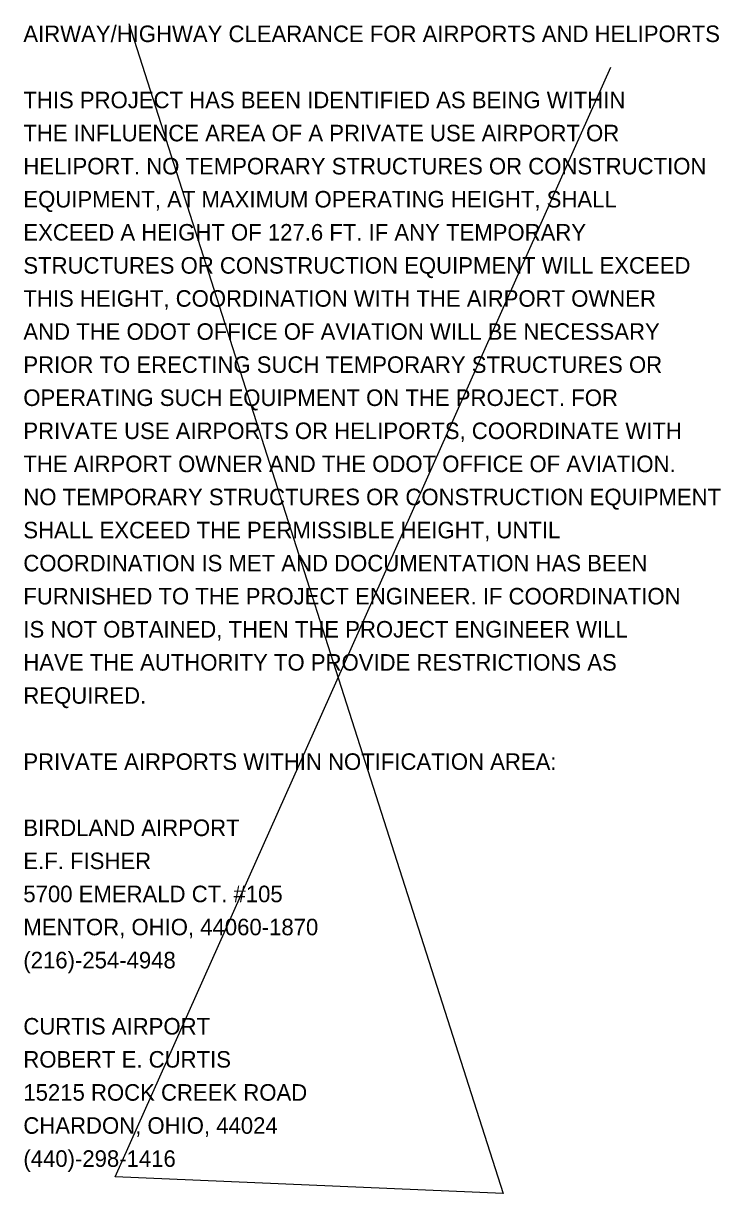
# Model space of a CAD drawing. Extents: x 0 to 55.9, y -18.9 to 33.1.
# Drawn here: x 49.99 to 55.9, y -18.87 to -8.96 of the extents above; entities that cross this region are included whole.
import ezdxf

# ---------------------------------------------------------------- set-up
doc = ezdxf.new("R2010")
doc.units = 0
doc.layers.add('SH_Text', color=7, linetype='Continuous')

msp = doc.modelspace()

# ---------------------------------------------------------------- linework, layer by layer
at = {"layer": 'SH_Text'}
msp.add_lwpolyline([(50.8855, -8.9619), (54.0546, -18.8663), (50.7683, -18.7247), (54.9666, -9.333)], dxfattribs=at)

# ---------------------------------------------------------------- texts
for s, p in [('AIRWAY/HIGHWAY CLEARANCE FOR AIRPORTS AND HELIPORTS', (49.9915, -9.12)), ('THIS PROJECT HAS BEEN IDENTIFIED AS BEING WITHIN', (49.9915, -9.68)), ('THE INFLUENCE AREA OF A PRIVATE USE AIRPORT OR', (49.9915, -9.96)), ('HELIPORT. NO TEMPORARY STRUCTURES OR CONSTRUCTION', (49.9915, -10.24)), ('EQUIPMENT, AT MAXIMUM OPERATING HEIGHT, SHALL', (49.9915, -10.52)), ('EXCEED A HEIGHT OF 127.6 FT. IF ANY TEMPORARY', (49.9915, -10.8)), ('STRUCTURES OR CONSTRUCTION EQUIPMENT WILL EXCEED', (49.9915, -11.08)), ('THIS HEIGHT, COORDINATION WITH THE AIRPORT OWNER', (49.9915, -11.36)), ('AND THE ODOT OFFICE OF AVIATION WILL BE NECESSARY', (49.9915, -11.64)), ('PRIOR TO ERECTING SUCH TEMPORARY STRUCTURES OR', (49.9915, -11.92)), ('OPERATING SUCH EQUIPMENT ON THE PROJECT. FOR', (49.9915, -12.2)), ('PRIVATE USE AIRPORTS OR HELIPORTS, COORDINATE WITH', (49.9915, -12.48)), ('THE AIRPORT OWNER AND THE ODOT OFFICE OF AVIATION.', (49.9915, -12.76)), ('NO TEMPORARY STRUCTURES OR CONSTRUCTION EQUIPMENT', (49.9915, -13.04)), ('SHALL EXCEED THE PERMISSIBLE HEIGHT, UNTIL', (49.9915, -13.32)), ('COORDINATION IS MET AND DOCUMENTATION HAS BEEN', (49.9915, -13.6)), ('FURNISHED TO THE PROJECT ENGINEER. IF COORDINATION', (49.9915, -13.88)), ('IS NOT OBTAINED, THEN THE PROJECT ENGINEER WILL', (49.9915, -14.16)), ('HAVE THE AUTHORITY TO PROVIDE RESTRICTIONS AS', (49.9915, -14.44)), ('REQUIRED.', (49.9915, -14.72)), ('PRIVATE AIRPORTS WITHIN NOTIFICATION AREA:', (49.9915, -15.28)), ('BIRDLAND AIRPORT', (49.9915, -15.84)), ('E.F. FISHER', (49.9915, -16.12)), ('5700 EMERALD CT. #105 ', (49.9915, -16.4)), ('MENTOR, OHIO, 44060-1870', (49.9915, -16.68)), ('(216)-254-4948', (49.9915, -16.96)), ('CURTIS AIRPORT', (49.9915, -17.52)), ('ROBERT E. CURTIS', (49.9915, -17.8)), ('15215 ROCK CREEK ROAD', (49.9915, -18.08)), ('CHARDON, OHIO, 44024', (49.9915, -18.36)), ('(440)-298-1416', (49.9915, -18.64))]:
    msp.add_text(s, height=0.14, dxfattribs=at).set_placement(p)

doc.saveas('drawing.dxf')
